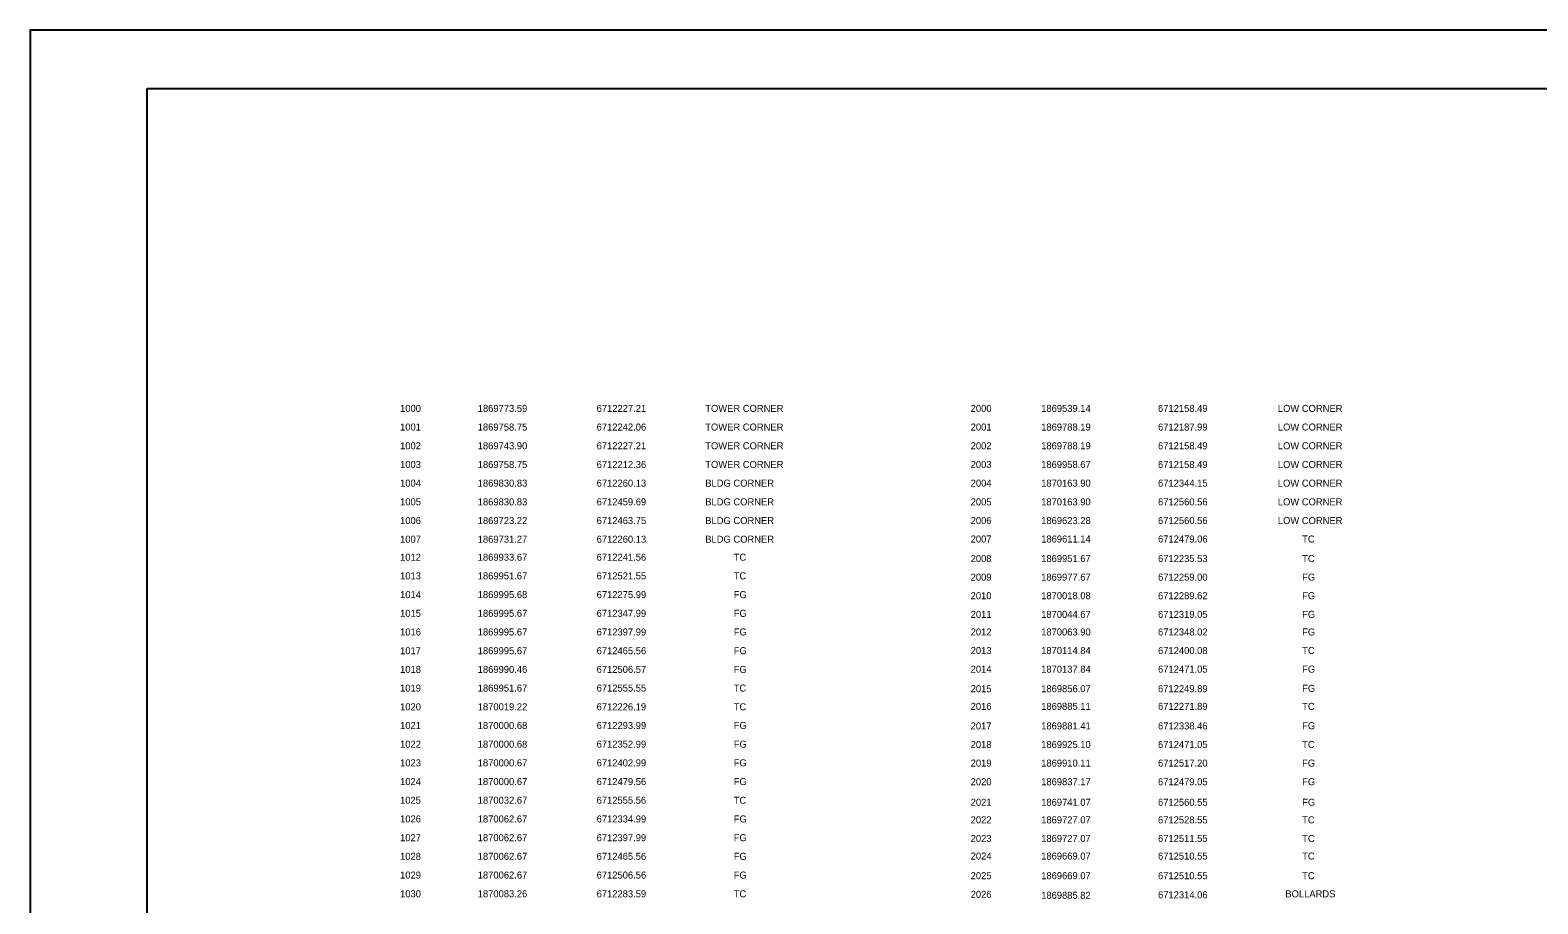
# Model space of a CAD drawing. Extents: x 0 to 4.36, y 0 to 2.5.
# Drawn here: x 0 to 2.15, y 1.254 to 2.5 of the extents above; entities that cross this region are included whole.
import ezdxf

# ---------------------------------------------------------------- set-up
doc = ezdxf.new("R2010")
doc.units = 0
for name, color, linetype in [('C-TEXT', 7, 'Continuous'), ('G-TTLB-OTLN', 7, 'Continuous'), ('G-TTLB-VIEW', 7, 'Continuous')]:
    doc.layers.add(name, color=color, linetype=linetype)

msp = doc.modelspace()

# ---------------------------------------------------------------- linework, layer by layer
at = {"layer": 'G-TTLB-OTLN'}
msp.add_lwpolyline([(0, 0), (3.5, 0), (3.5, 2.5), (0, 2.5)], close=True, dxfattribs=at)
at = {"layer": 'G-TTLB-VIEW'}
msp.add_lwpolyline([(0.1667, 2.4167), (3.0729, 2.4167), (3.0729, 0.0833), (0.1667, 0.0833)], close=True, dxfattribs=at)

# ---------------------------------------------------------------- texts
at = {"layer": 'C-TEXT'}
for s, p in [('1000', (0.5274, 1.9555)), ('1869773.59', (0.6381, 1.9555)), ('6712227.21', (0.8076, 1.9555)), ('TOWER CORNER', (0.9625, 1.9555)), ('2000', (1.3409, 1.9555)), ('1869539.14', (1.4414, 1.9555)), ('6712158.49', (1.608, 1.9555)), ('LOW CORNER', (1.7788, 1.9555)), ('1001', (0.5274, 1.9289)), ('1869758.75', (0.6381, 1.9289)), ('6712242.06', (0.8076, 1.9289)), ('TOWER CORNER', (0.9625, 1.9289)), ('2001', (1.3409, 1.9289)), ('1869788.19', (1.4414, 1.9289)), ('6712187.99', (1.608, 1.9289)), ('LOW CORNER', (1.7788, 1.9289)), ('1002', (0.5274, 1.9022)), ('1869743.90', (0.6381, 1.9022)), ('6712227.21', (0.8076, 1.9022)), ('TOWER CORNER', (0.9625, 1.9022)), ('2002', (1.3409, 1.9022)), ('1869788.19', (1.4414, 1.9022)), ('6712158.49', (1.608, 1.9022)), ('LOW CORNER', (1.7788, 1.9022)), ('1003', (0.5274, 1.8755)), ('1869758.75', (0.6381, 1.8755)), ('6712212.36', (0.8076, 1.8755)), ('TOWER CORNER', (0.9625, 1.8755)), ('2003', (1.3409, 1.8755)), ('1869958.67', (1.4414, 1.8755)), ('6712158.49', (1.608, 1.8755)), ('LOW CORNER', (1.7788, 1.8755)), ('1004', (0.5274, 1.8489)), ('1869830.83', (0.6381, 1.8489)), ('6712260.13', (0.8076, 1.8489)), ('BLDG CORNER', (0.9625, 1.8489)), ('2004', (1.3409, 1.8489)), ('1870163.90', (1.4414, 1.8489)), ('6712344.15', (1.608, 1.8489)), ('LOW CORNER', (1.7788, 1.8489)), ('1005', (0.5274, 1.8222)), ('1869830.83', (0.6381, 1.8222)), ('6712459.69', (0.8076, 1.8222)), ('BLDG CORNER', (0.9625, 1.8222)), ('2005', (1.3409, 1.8222)), ('1870163.90', (1.4414, 1.8222)), ('6712560.56', (1.608, 1.8222)), ('LOW CORNER', (1.7788, 1.8222)), ('1006', (0.5274, 1.7955)), ('1869723.22', (0.6381, 1.7955)), ('6712463.75', (0.8076, 1.7955)), ('BLDG CORNER', (0.9625, 1.7955)), ('2006', (1.3409, 1.7955)), ('1869623.28', (1.4414, 1.7955)), ('6712560.56', (1.608, 1.7955)), ('LOW CORNER', (1.7788, 1.7955)), ('1007', (0.5274, 1.7689)), ('1869731.27', (0.6381, 1.7689)), ('6712260.13', (0.8076, 1.7689)), ('BLDG CORNER', (0.9625, 1.7689)), ('2007', (1.3409, 1.7692)), ('1869611.14', (1.4414, 1.7692)), ('6712479.06', (1.608, 1.7692)), ('TC', (1.8135, 1.7692)), ('1012', (0.5274, 1.7432)), ('1869933.67', (0.6381, 1.7432)), ('6712241.56', (0.8076, 1.7432)), ('TC', (1.0031, 1.7432)), ('2008', (1.3409, 1.7413)), ('1869951.67', (1.4414, 1.7413)), ('6712235.53', (1.608, 1.7413)), ('TC', (1.8135, 1.7413)), ('1013', (0.5274, 1.7166)), ('1869951.67', (0.6381, 1.7166)), ('6712521.55', (0.8076, 1.7166)), ('TC', (1.0031, 1.7166)), ('2009', (1.3409, 1.7148)), ('1869977.67', (1.4414, 1.7148)), ('6712259.00', (1.608, 1.7148)), ('FG', (1.8135, 1.7148)), ('1014', (0.5274, 1.6899)), ('1869995.68', (0.6381, 1.6899)), ('6712275.99', (0.8076, 1.6899)), ('FG', (1.0031, 1.6899)), ('2010', (1.3409, 1.6883)), ('1870018.08', (1.4414, 1.6883)), ('6712289.62', (1.608, 1.6883)), ('FG', (1.8135, 1.6883)), ('1015', (0.5274, 1.6632)), ('1869995.67', (0.6381, 1.6632)), ('6712347.99', (0.8076, 1.6632)), ('FG', (1.0031, 1.6632)), ('2011', (1.3409, 1.6617)), ('1870044.67', (1.4414, 1.6617)), ('6712319.05', (1.608, 1.6617)), ('FG', (1.8135, 1.6617)), ('1016', (0.5274, 1.6366)), ('1869995.67', (0.6381, 1.6366)), ('6712397.99', (0.8076, 1.6366)), ('FG', (1.0031, 1.6366)), ('2012', (1.3409, 1.6366)), ('1870063.90', (1.4414, 1.6366)), ('6712348.02', (1.608, 1.6366)), ('FG', (1.8135, 1.6366)), ('1017', (0.5274, 1.6099)), ('1869995.67', (0.6381, 1.6099)), ('6712465.56', (0.8076, 1.6099)), ('FG', (1.0031, 1.6099)), ('2013', (1.3409, 1.6101)), ('1870114.84', (1.4414, 1.6101)), ('6712400.08', (1.608, 1.6101)), ('TC', (1.8135, 1.6101)), ('1018', (0.5274, 1.5832)), ('1869990.46', (0.6381, 1.5832)), ('6712506.57', (0.8076, 1.5832)), ('FG', (1.0031, 1.5832)), ('2014', (1.3409, 1.5836)), ('1870137.84', (1.4414, 1.5836)), ('6712471.05', (1.608, 1.5836)), ('FG', (1.8135, 1.5836)), ('1019', (0.5274, 1.5566)), ('1869951.67', (0.6381, 1.5566)), ('6712555.55', (0.8076, 1.5566)), ('TC', (1.0031, 1.5566)), ('2015', (1.3409, 1.5557)), ('1869856.07', (1.4414, 1.5557)), ('6712249.89', (1.608, 1.5557)), ('FG', (1.8135, 1.5562)), ('1020', (0.5274, 1.5299)), ('1870019.22', (0.6381, 1.5299)), ('6712226.19', (0.8076, 1.5299)), ('TC', (1.0031, 1.5299)), ('2016', (1.3409, 1.5305)), ('1869885.11', (1.4414, 1.5305)), ('6712271.89', (1.608, 1.5305)), ('TC', (1.8135, 1.5305)), ('1021', (0.5274, 1.5032)), ('1870000.68', (0.6381, 1.5032)), ('6712293.99', (0.8076, 1.5032)), ('FG', (1.0031, 1.5032)), ('2017', (1.3409, 1.5026)), ('1869881.41', (1.4414, 1.5026)), ('6712338.46', (1.608, 1.5026)), ('FG', (1.8135, 1.5029)), ('1022', (0.5274, 1.4766)), ('1870000.68', (0.6381, 1.4766)), ('6712352.99', (0.8076, 1.4766)), ('FG', (1.0031, 1.4766)), ('2018', (1.3409, 1.4761)), ('1869925.10', (1.4414, 1.4761)), ('6712471.05', (1.608, 1.4761)), ('TC', (1.8135, 1.4761)), ('1023', (0.5274, 1.4499)), ('1870000.67', (0.6381, 1.4499)), ('6712402.99', (0.8076, 1.4499)), ('FG', (1.0031, 1.4499)), ('2019', (1.3409, 1.4496)), ('1869910.11', (1.4414, 1.4496)), ('6712517.20', (1.608, 1.4496)), ('FG', (1.8135, 1.4496)), ('1024', (0.5274, 1.4232)), ('1870000.67', (0.6381, 1.4232)), ('6712479.56', (0.8076, 1.4232)), ('FG', (1.0031, 1.4232)), ('2020', (1.3409, 1.423)), ('1869837.17', (1.4414, 1.423)), ('6712479.05', (1.608, 1.423)), ('FG', (1.8135, 1.423)), ('1025', (0.5274, 1.3966)), ('1870032.67', (0.6381, 1.3966)), ('6712555.56', (0.8076, 1.3966)), ('TC', (1.0031, 1.3966)), ('2021', (1.3409, 1.3937)), ('1869741.07', (1.4414, 1.3937)), ('6712560.55', (1.608, 1.3937)), ('FG', (1.8135, 1.3937)), ('1026', (0.5274, 1.3699)), ('1870062.67', (0.6381, 1.3699)), ('6712334.99', (0.8076, 1.3699)), ('FG', (1.0031, 1.3699)), ('2022', (1.3409, 1.3686)), ('1869727.07', (1.4414, 1.3686)), ('6712528.55', (1.608, 1.3686)), ('TC', (1.8135, 1.3686)), ('1027', (0.5274, 1.3432)), ('1870062.67', (0.6381, 1.3432)), ('6712397.99', (0.8076, 1.3432)), ('FG', (1.0031, 1.3432)), ('2023', (1.3409, 1.3421)), ('1869727.07', (1.4414, 1.3421)), ('6712511.55', (1.608, 1.3421)), ('TC', (1.8135, 1.3421)), ('1028', (0.5274, 1.3166)), ('1870062.67', (0.6381, 1.3166)), ('6712465.56', (0.8076, 1.3166)), ('FG', (1.0031, 1.3166)), ('2024', (1.3409, 1.317)), ('1869669.07', (1.4414, 1.317)), ('6712510.55', (1.608, 1.317)), ('TC', (1.8135, 1.317)), ('1029', (0.5274, 1.2899)), ('1870062.67', (0.6381, 1.2899)), ('6712506.56', (0.8076, 1.2899)), ('FG', (1.0031, 1.2899)), ('2025', (1.3409, 1.289)), ('1869669.07', (1.4414, 1.289)), ('6712510.55', (1.608, 1.289)), ('TC', (1.8135, 1.289)), ('1030', (0.5274, 1.2632)), ('1870083.26', (0.6381, 1.2632)), ('6712283.59', (0.8076, 1.2632)), ('TC', (1.0031, 1.2632)), ('2026', (1.3409, 1.2624)), ('1869885.82', (1.4414, 1.261)), ('6712314.06', (1.608, 1.2617)), ('BOLLARDS', (1.7895, 1.2631))]:
    msp.add_text(s, height=0.01, dxfattribs=at).set_placement(p)

doc.saveas('drawing.dxf')
